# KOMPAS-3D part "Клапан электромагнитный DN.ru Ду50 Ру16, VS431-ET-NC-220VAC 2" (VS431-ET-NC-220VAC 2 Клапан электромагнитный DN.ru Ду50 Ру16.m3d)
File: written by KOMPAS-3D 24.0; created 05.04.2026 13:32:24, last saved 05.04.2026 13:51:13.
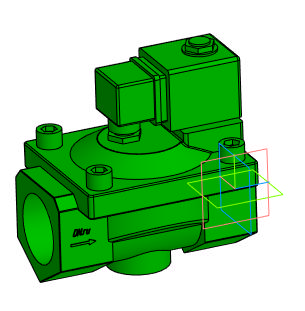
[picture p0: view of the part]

Document properties: Автор: artio; Полное имя файла: C:\Users\artio\OneDrive\Рабочий стол\Клапан электромагнитный DN.ru\VS431\VS431-ET-NC\VS431-ET-NC-220VAC\Ду50\VS431-ET-NC-220VAC 2 Клапан электромагнитный DN.ru Ду50 Ру16.m3d

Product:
- Body: Тело 1  | qty 1
    Масса: 6.703651
- Part/product: Клапан электромагнитный DN.ru Ду50 Ру16  | designation VS431-ET-NC-220VAC 2
    Масса: 3.341
    Раздел спецификации: Прочие изделия
    Примечание: D130-04710
    additional columns: ef56311e-7521-43dc-8291-0e6108b3d81d; artio; c; Шероховатость не задана; Да

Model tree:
1. Операция без истории:1

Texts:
  VS431-ET-NC-220VAC 2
